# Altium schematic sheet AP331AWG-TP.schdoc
size 127 x 101 mm
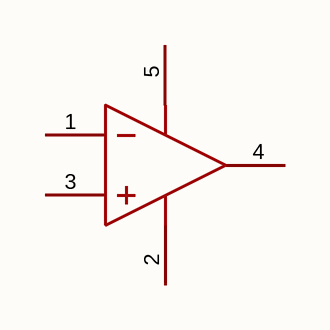
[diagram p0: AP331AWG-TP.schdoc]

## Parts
U?  ap331awg-tp  [SOT-23-5_L2.9-W1.6-P0.95-LS2.8-BR]  (value not drawn)

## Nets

Not connected (* = marked no-connect by the designer): U? 1(IN_-) 2(GND) 3(IN_+) 4(OUT) 5(VCC)

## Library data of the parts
U? = ap331awg-tp: 比较器数:单路;输入失调电压(Vos):2mV;输入偏置电流(Ib):25nA;; Manufacturer: TECH PUBLIC(台舟); AddInBom: yes; ModelId: 7ba65df16e7b4570af156e925f9c37fe; ModelTransform: 114.173,114.173,0,90,0,0,0,0,0; Number of Channels: 单路; Vos - Input Offset Voltage: 2mV; Ib - Input Bias Current: 25nA; Propagation Delay Time: 300ns; Output Mode: CMOS；TTL; Quiescent Current: 400uA; Maximum Power Supply Range (Vdd-Vss): 36V; Single Supply: 2V~36V; Dual Supply: -18V~-1V；1V~18V; Input Offset Current(Ios): 0.5nA; Response Time (tr): 1.3us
